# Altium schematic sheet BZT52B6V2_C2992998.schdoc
size 127 x 101 mm
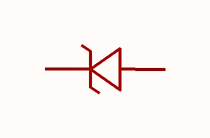
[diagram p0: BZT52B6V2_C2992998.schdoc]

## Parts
D?  bzt52b6v2_c2992998  [SOD-123_L2.7-W1.6-LS3.7-RD]  (value not drawn)

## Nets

Not connected (* = marked no-connect by the designer): D? 1(C) 2(A)

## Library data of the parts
D? = bzt52b6v2_c2992998: 二极管配置:1个独立式;稳压值(标称值):6.2V;稳压值(范围):6.08V~6.32V;耗散功率(Pd):500mW;; Manufacturer: MDD(辰达半导体); AddInBom: yes; ModelId: ad7e39f9e5534b3c96ffdc5532ebb493; ModelName: SOD-123_L2.7-W1.6-H1.4-LS3.7; ModelTransform: 146.026,62.992,0,180,0,0,0.0005,0,0; Diode Configuration: 1个独立式; Zener Voltage(Nom): 6.2V; Reverse Leakage Current (Ir): 1uA@3V; Pd - Power Dissipation: 500mW; Impedance(Zzt): 50Ω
